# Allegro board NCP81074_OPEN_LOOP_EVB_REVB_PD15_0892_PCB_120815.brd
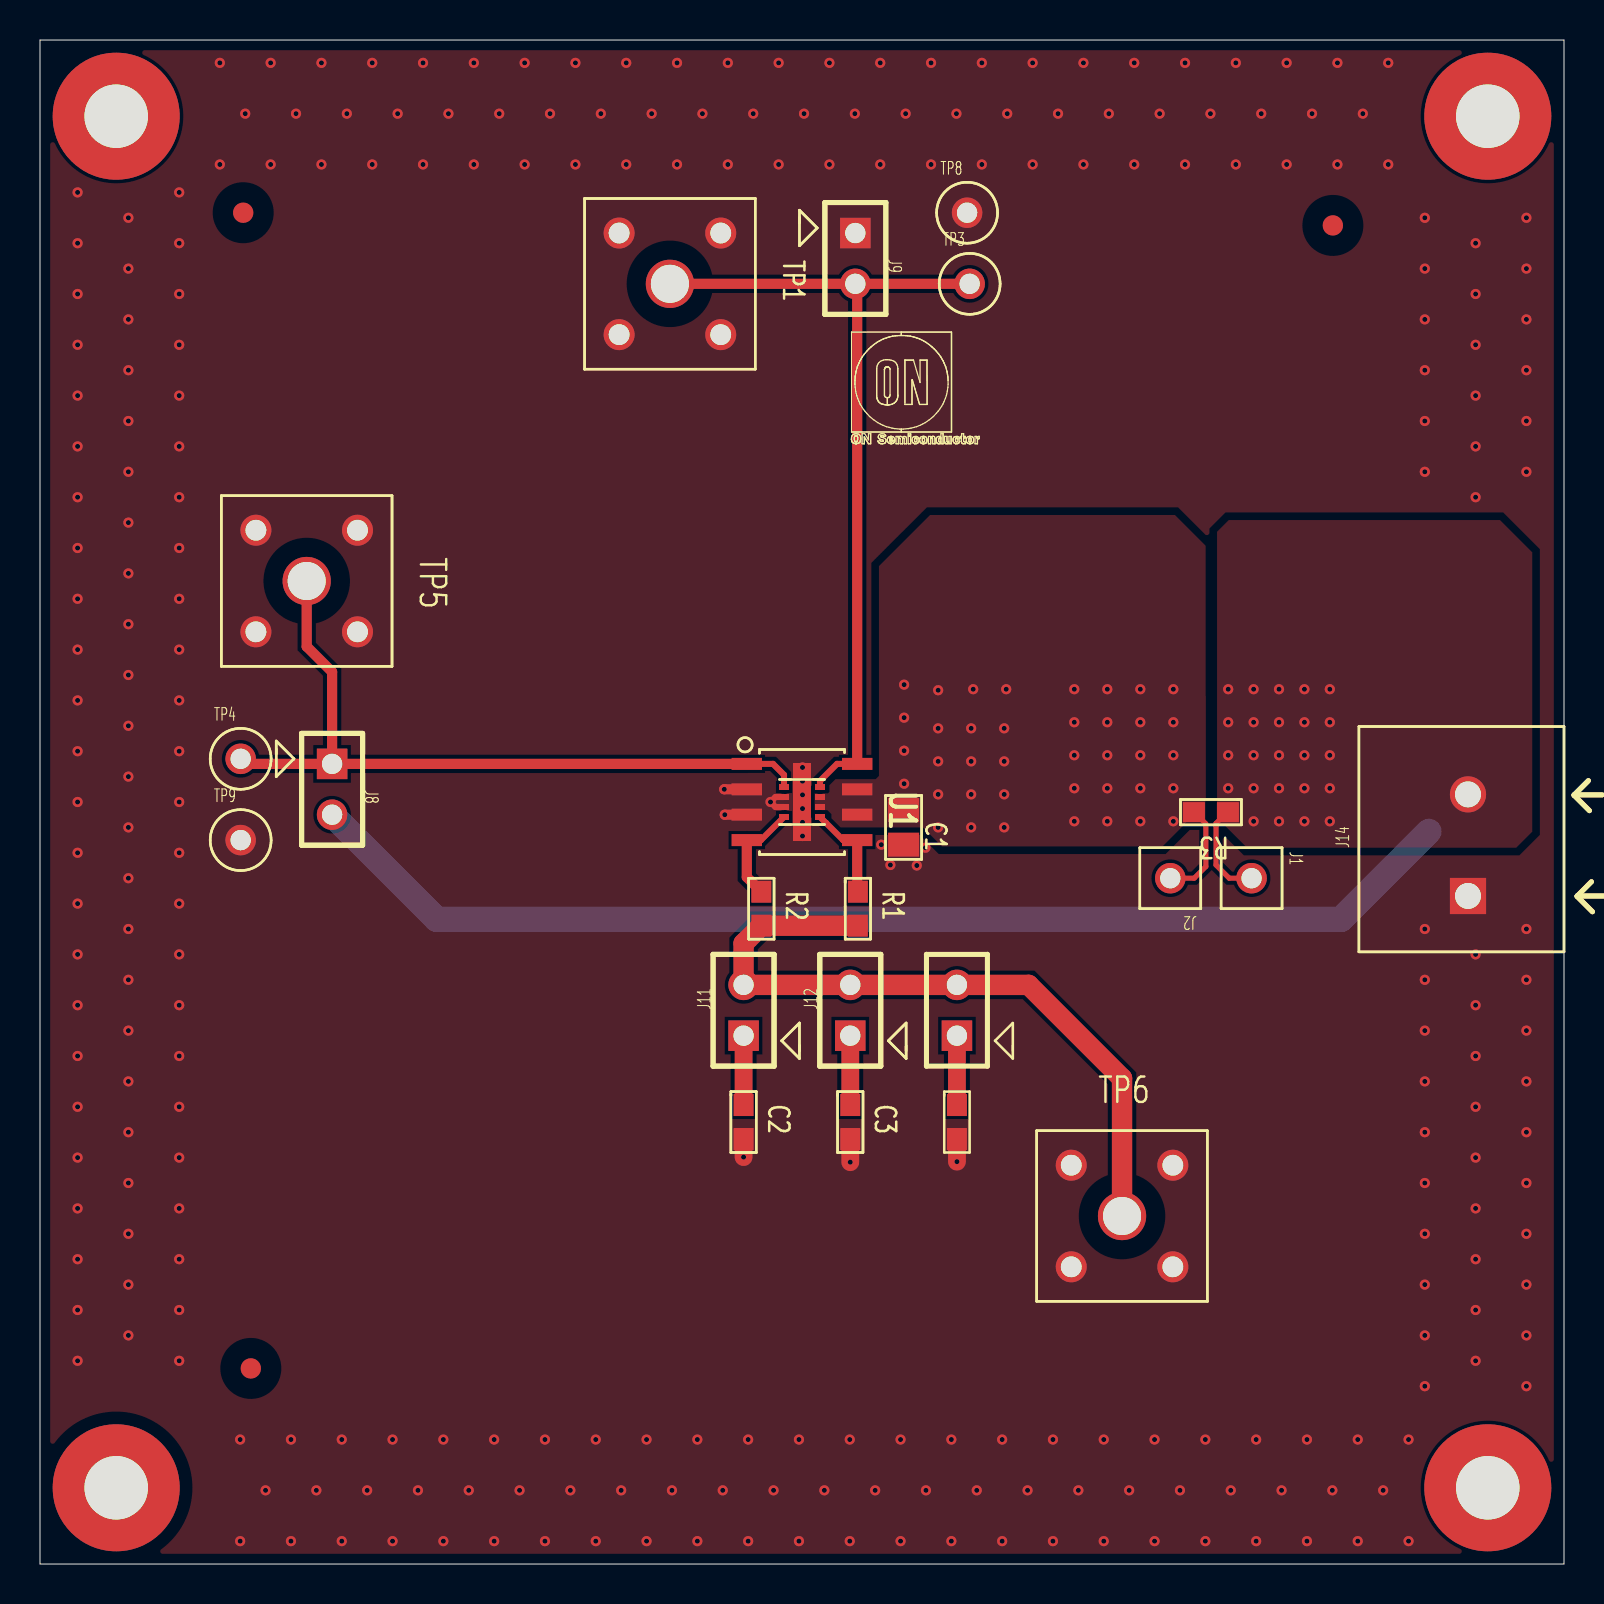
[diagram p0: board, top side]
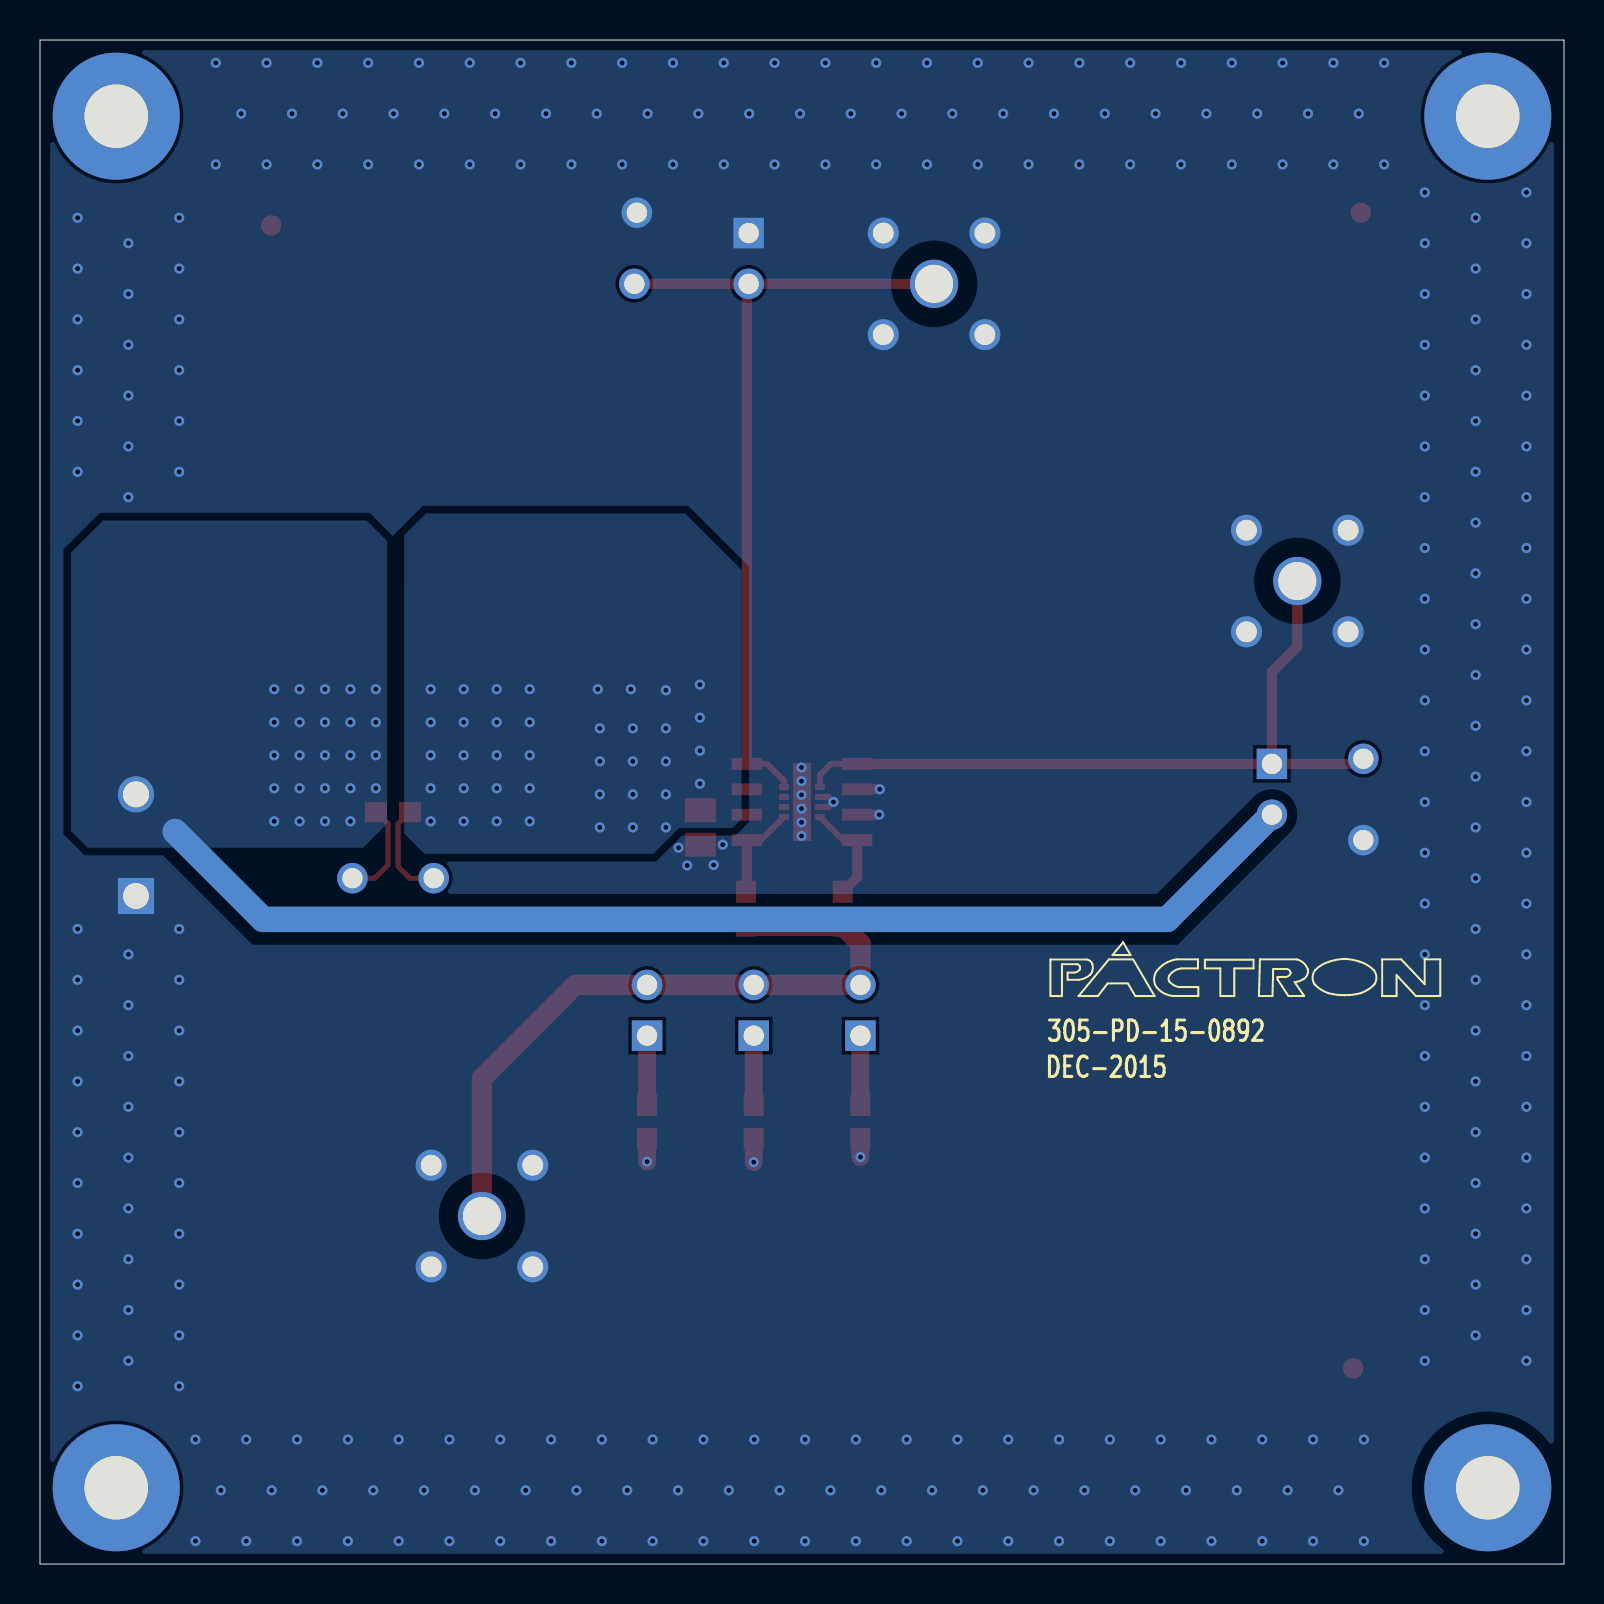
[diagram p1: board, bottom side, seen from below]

Outline 76.2 x 76.2 mm; copper layers: TOP, GND1#2, GND2#3, BOTTOM. Coordinates in mm from the lower left corner of the outline.
Outline path: 0,76.2 0,0 76.2,0 76.2,76.2 0,76.2

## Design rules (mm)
constraint set DEFAULT: min track width 0.254

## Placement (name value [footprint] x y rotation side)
C1  4.7uf  [0805]  43.18 36.83 270 top
C2  1nF  [0603]  35.18 22.1 270 top
C3  1.8nF  [0603]  40.51 22.1 270 top
C4  1.8nF  [0603]  45.85 22.1 270 top
J1  TP  [TRM1]  60.58 34.29 270 top
J2  TP  [TRM1]  56.52 34.29 180 top
J8  PEC36SAAN  [TERM3]  14.61 40.01 270 top
J9  PEC36SAAN  [TERM3]  40.77 66.55 270 top
J11  PEC36SAAN  [TERM3]  35.18 26.42 90 top
J12  PEC36SAAN  [TERM3]  40.51 26.42 90 top
J13  PEC36SAAN  [TERM3]  45.85 26.42 90 top
J14  2PIN/TERM BLK  [TRM2]  71.4 35.94 90 top
NOREF  -  []  76.2 76.2 0 top
NOREF#2  -  []  72.39 72.39 0 top
NOREF#3  -  [unnamed#2]  10.54 9.78 0 top
NOREF#4  -  [unnamed#2]  72.39 3.81 0 top
NOREF#5  -  [unnamed#2]  72.39 72.39 0 top
NOREF#6  -  [unnamed#2]  64.64 66.93 0 top
NOREF#7  -  [unnamed#2]  3.81 72.39 0 top
NOREF#8  -  []  72.39 72.39 0 top
NOREF#9  -  [unnamed#2]  3.81 3.81 0 top
NOREF#10  -  []  0 0 0 top
NOREF#11  -  [unnamed#2]  10.16 67.56 0 top
NOREF#12  -  []  0 0 0 top
NOREF#13  -  []  76.2 76.2 0 top
R1  1 OHM  [0603]  40.89 32.77 270 top
R2  1 OHM  [0603]  36.07 32.77 270 top
R3  0.1  [0603]  58.55 37.59 180 top
TP1  Probe Ground Tip  [SMA]  31.5 64.01 270 top
TP3  T POINT R  [TP40_60]  46.48 64.01 0 top
TP4  T POINT R  [TP40_60]  10.03 40.26 0 top
TP5  Probe Ground Tip  [SMA]  13.34 49.15 270 top
TP6  Probe Ground Tip  [SMA]  54.1 17.4 0 top
TP8  T POINT R  [TP40_60]  46.35 67.56 0 top
TP9  T POINT R  [TP40_60]  10.03 36.2 0 top
U1  NCP81074  [DFN8]  38.1 38.1 270 top

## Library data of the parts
C1 = CAP
C2-C4 = C
J1 J2 = TP_SQUARE
J8 J9 J11-J13 = JUMPER
J14 = Term_Blk_2_0.2
R1-R3 = R
TP1 TP5 TP6 = BNC_0
TP3 TP4 TP8 TP9 = T POINT R
U1 = ADP3418_4

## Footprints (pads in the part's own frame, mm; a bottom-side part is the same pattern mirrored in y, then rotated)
0603
  rect 1.1x1 smd: 1(-0.85,0) 2(0.85,0)
0805
  rect 1.2x1.55 smd: 1(-0.865,0) 2(0.865,0)
DFN8
  rect 0.6x1.52 smd: 1(-1.905,-2.76) 2(-0.635,-2.76) 3(0.635,-2.76) 4(1.905,-2.76) 5(1.905,2.76) 6(0.635,2.76) 7(-0.635,2.76) 8(-1.905,2.76)
  rect 0.3x0.5 smd: 1A(-0.75,-0.9) 2A(-0.25,-0.9) 3A(0.25,-0.9) 4A(0.75,-0.9) 5A(0.75,0.9) 6A(0.25,0.9) 7A(-0.25,0.9) 8A(-0.75,0.9)
  rect 3.9x0.9 smd: 9(0,0)
SMA
  round 2.413 hole 1.905: 1(0,0)
  round 1.549 hole 1.041: 2(2.54,-2.54) 3(2.54,2.54) 4(-2.54,2.54) 5(-2.54,-2.54)
TERM3
  rect 1.524x1.524 hole 1.016: 1(0,0)
  round 1.524 hole 1.016: 2(2.54,0)
TP40_60
  round 1.524 hole 1.016: 1(0,0)
TRM1
  round 1.524 hole 1.016: 1(0,0)
TRM2
  rect 1.808x1.808 hole 1.3: 1(-2.54,0)
  round 1.808 hole 1.3: 2(2.54,0)
unnamed#2
  round 1.016 smd: (0,0)

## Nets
12V: J1.1 J8.2 J14.2 R3.1
GND: C1.2 C2.2 C3.2 C4.2 J9.1 J14.1 TP1.2 TP1.3 TP1.4 TP1.5(SHIELD5) TP5.2 TP5.3 TP5.4 TP5.5(SHIELD5) TP6.2 TP6.3 TP6.4 TP6.5(SHIELD5) TP8.1(TP) TP9.1(TP) U1.2 U1.2A U1.3 U1.3A U1.9
N59573: C1.1 J2.1 R3.2 U1.6 U1.6A(VDDA) U1.7 U1.7A
N59818: J9.2 TP1.1 TP3.1(TP) U1.8 U1.8A
N60576: R2.1 U1.4 U1.4A
N60580: J11.2 J12.2 J13.2 R1.2 R2.2 TP6.1
N60608: R1.1 U1.5 U1.5A
N60828: C3.1 J12.1
N60830: C4.1 J13.1
N60852: C2.1 J11.1
N68500: J8.1 TP4.1(TP) TP5.1 U1.1 U1.1A

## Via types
v1: diameter 0.508, hole 0.254, TOP to BOTTOM, 339 vias

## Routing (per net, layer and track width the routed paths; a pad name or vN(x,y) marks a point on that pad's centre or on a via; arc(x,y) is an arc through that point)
12V: length 63.8
  TOP w0.254: J1.1 59.46,34.29 58.8,34.95 58.8,37.03 59.36,37.59 R3.1
  BOTTOM w1.27: 69.44,36.63 65.05,32.23 19.84,32.23 J8.2
  vias: v1(59.41,43.74) v1(59.41,42.09) v1(59.41,40.44) v1(59.41,38.79) v1(60.68,43.74) v1(60.68,42.09) v1(60.68,40.44) v1(60.68,38.79) v1(60.68,37.13) v1(61.95,43.74) v1(61.95,42.09) v1(61.95,40.44) v1(61.95,38.79) v1(61.95,37.13) v1(63.22,43.74) v1(63.22,42.09) v1(63.22,40.44) v1(63.22,38.79) v1(63.22,37.13) v1(64.49,43.74) v1(64.49,42.09) v1(64.49,40.44) v1(64.49,38.79) v1(64.49,37.13)
GND: length 7
  TOP w0.305: U1.2A 36.78,38.35 v1(36.53,38.1) 36.78,37.85 U1.3A
  TOP w0.508: U1.3 v1(34.24,37.47) ; U1.2 v1(34.21,38.73)
  TOP w0.889: C2.2 v1(35.18,20.35) ; C3.2 v1(40.51,20.09) ; C4.2 v1(45.85,20.12)
  vias: v1(1.88,68.58) v1(1.88,66.04) v1(1.88,63.5) v1(1.88,60.96) v1(1.88,58.42) v1(1.88,55.88) v1(1.88,53.34) v1(1.88,50.8) v1(1.88,48.26) v1(1.88,45.72) v1(1.88,43.18) v1(1.88,40.64) v1(1.88,38.1) v1(1.88,35.56) v1(1.88,33.02) v1(1.88,30.48) v1(1.88,27.94) v1(1.88,25.4) v1(1.88,22.86) v1(1.88,20.32) v1(1.88,17.78) v1(1.88,15.24) v1(1.88,12.7) v1(1.88,10.16) v1(4.42,67.31) v1(4.42,64.77) v1(4.42,62.23) v1(4.42,59.69) v1(4.42,57.15) v1(4.42,54.61) v1(4.42,52.07) v1(4.42,49.53) v1(4.42,46.99) v1(4.42,44.45) v1(4.42,41.91) v1(4.42,39.37) v1(4.42,36.83) v1(4.42,34.29) v1(4.42,31.75) v1(4.42,29.21) v1(4.42,26.67) v1(4.42,24.13) v1(4.42,21.59) v1(4.42,19.05) v1(4.42,16.51) v1(4.42,13.97) v1(4.42,11.43) v1(6.96,68.58) v1(6.96,66.04) v1(6.96,63.5) v1(6.96,60.96) v1(6.96,58.42) v1(6.96,55.88) v1(6.96,53.34) v1(6.96,50.8) v1(6.96,48.26) v1(6.96,45.72) v1(6.96,43.18) v1(6.96,40.64) v1(6.96,38.1) v1(6.96,35.56) v1(6.96,33.02) v1(6.96,30.48) v1(6.96,27.94) v1(6.96,25.4) v1(6.96,22.86) v1(6.96,20.32) v1(6.96,17.78) v1(6.96,15.24) v1(6.96,12.7) v1(6.96,10.16) v1(8.99,75.06) v1(8.99,69.98) v1(10.01,6.22) v1(10.01,1.14) v1(10.26,72.52) v1(11.28,3.68) v1(11.53,75.06) v1(11.53,69.98) v1(12.55,6.22) v1(12.55,1.14) v1(12.8,72.52) v1(13.82,3.68) v1(14.07,75.06) v1(14.07,69.98) v1(15.09,6.22) v1(15.09,1.14) v1(15.34,72.52) v1(16.36,3.68) v1(16.61,75.06) v1(16.61,69.98) v1(17.63,6.22) v1(17.63,1.14) v1(17.88,72.52) v1(18.9,3.68) v1(19.15,75.06) v1(19.15,69.98) v1(20.17,6.22) v1(20.17,1.14) v1(20.42,72.52) v1(21.44,3.68) v1(21.69,75.06) v1(21.69,69.98) v1(22.71,6.22) v1(22.71,1.14) v1(22.96,72.52) v1(23.98,3.68) v1(24.23,75.06) v1(24.23,69.98) v1(25.25,6.22) v1(25.25,1.14) v1(25.5,72.52) v1(26.52,3.68) v1(26.77,75.06) v1(26.77,69.98) v1(27.79,6.22) v1(27.79,1.14) v1(28.04,72.52) v1(29.06,3.68) v1(29.31,75.06) v1(29.31,69.98) v1(30.33,6.22) v1(30.33,1.14) v1(30.58,72.52) v1(31.6,3.68) v1(31.85,75.06) v1(31.85,69.98) v1(32.87,6.22) v1(32.87,1.14) v1(33.12,72.52) v1(34.14,3.68) v1(34.39,75.06) v1(34.39,69.98) v1(35.41,6.22) v1(35.41,1.14) v1(35.66,72.52) v1(36.68,3.68) v1(36.93,75.06) v1(36.93,69.98) v1(37.95,6.22) v1(37.95,1.14) v1(38.13,39.83) v1(38.13,39.14) v1(38.13,38.46) v1(38.13,37.77) v1(38.13,37.08) v1(38.13,36.4) v1(38.2,72.52) v1(39.22,3.68) v1(39.47,75.06) v1(39.47,69.98) v1(40.49,6.22) v1(40.49,1.14) v1(40.74,72.52) v1(41.76,3.68) v1(42.01,75.06) v1(42.01,69.98) v1(42.06,35.97) v1(42.52,34.95) v1(43.03,6.22) v1(43.03,1.14) v1(43.28,72.52) v1(43.84,34.92) v1(44.27,35.81) v1(44.3,3.68) v1(44.55,75.06) v1(44.55,69.98) v1(45.57,6.22) v1(45.57,1.14) v1(45.82,72.52) v1(46.84,3.68) v1(47.09,75.06) v1(47.09,69.98) v1(48.11,6.22) v1(48.11,1.14) v1(48.36,72.52) v1(49.38,3.68) v1(49.63,75.06) v1(49.63,69.98) v1(50.65,6.22) v1(50.65,1.14) v1(50.9,72.52) v1(51.92,3.68) v1(52.17,75.06) v1(52.17,69.98) v1(53.19,6.22) v1(53.19,1.14) v1(53.44,72.52) v1(54.46,3.68) v1(54.71,75.06) v1(54.71,69.98) v1(55.73,6.22) v1(55.73,1.14) v1(55.98,72.52) v1(57,3.68) v1(57.25,75.06) v1(57.25,69.98) v1(58.27,6.22) v1(58.27,1.14) v1(58.52,72.52) v1(59.54,3.68) v1(59.79,75.06) v1(59.79,69.98) v1(60.81,6.22) v1(60.81,1.14) v1(61.06,72.52) v1(62.08,3.68) v1(62.33,75.06) v1(62.33,69.98) v1(63.35,6.22) v1(63.35,1.14) v1(63.6,72.52) v1(64.62,3.68) v1(64.87,75.06) v1(64.87,69.98) v1(65.89,6.22) v1(65.89,1.14) v1(66.14,72.52) v1(67.16,3.68) v1(67.41,75.06) v1(67.41,69.98) v1(68.43,6.22) v1(68.43,1.14) v1(69.24,67.31) v1(69.24,64.77) v1(69.24,62.23) v1(69.24,59.69) v1(69.24,57.15) v1(69.24,54.61) v1(69.24,31.75) v1(69.24,29.21) v1(69.24,26.67) v1(69.24,24.13) v1(69.24,21.59) v1(69.24,19.05) v1(69.24,16.51) v1(69.24,13.97) v1(69.24,11.43) v1(69.24,8.89) v1(71.78,66.04) v1(71.78,63.5) v1(71.78,60.96) v1(71.78,58.42) v1(71.78,55.88) v1(71.78,53.34) v1(71.78,30.48) v1(71.78,27.94) v1(71.78,25.4) v1(71.78,22.86) v1(71.78,20.32) v1(71.78,17.78) v1(71.78,15.24) v1(71.78,12.7) v1(71.78,10.16) v1(74.32,67.31) v1(74.32,64.77) v1(74.32,62.23) v1(74.32,59.69) v1(74.32,57.15) v1(74.32,54.61) v1(74.32,31.75) v1(74.32,29.21) v1(74.32,26.67) v1(74.32,24.13) v1(74.32,21.59) v1(74.32,19.05) v1(74.32,16.51) v1(74.32,13.97) v1(74.32,11.43) v1(74.32,8.89)
N59573: length 5
  TOP w0.254: R3.2 57.71,37.59 58.29,37.01 58.29,34.87 57.71,34.29 J2.1
  vias: v1(43.21,43.97) v1(43.21,42.32) v1(43.21,40.67) v1(43.21,39.01) v1(44.91,43.69) v1(44.91,41.78) v1(44.91,40.13) v1(44.91,38.48) v1(44.91,36.83) v1(46.56,41.78) v1(46.56,40.13) v1(46.56,38.48) v1(46.56,36.83) v1(46.66,43.74) v1(48.21,41.78) v1(48.21,40.13) v1(48.21,38.48) v1(48.21,36.83) v1(48.31,43.74) v1(51.71,43.74) v1(51.71,42.09) v1(51.71,40.44) v1(51.71,38.79) v1(51.71,37.13) v1(53.37,43.74) v1(53.37,42.09) v1(53.37,40.44) v1(53.37,38.79) v1(53.37,37.13) v1(55.02,43.74) v1(55.02,42.09) v1(55.02,40.44) v1(55.02,38.79) v1(55.02,37.13) v1(56.67,43.74) v1(56.67,42.09) v1(56.67,40.44) v1(56.67,38.79) v1(56.67,37.13)
N59818: length 41.5
  TOP w0.305: U1.8 39.85,40.01 39,39.15 U1.8A
  TOP w0.508: U1.8 40.86,63.92 J9.2 ; TP3.1 J9.2 ; J9.2 TP1.1
N60576: length 5.2
  TOP w0.305: U1.4 36.05,36.2 U1.4A
  TOP w0.508: R2.1 35.34,34.34 U1.4
N60580: length 35.9
  TOP w1.016: R1.2 R2.2 35.18,31.03 J11.2 J12.2 J13.2 49.43,28.96 54.1,24.28 TP6.1
N60608: length 4.9
  TOP w0.305: U1.5 40.16,36.2 39.29,37.06 39.29,37.06 U1.5A
  TOP w0.508: U1.5 40.86,33.65 R1.1
N60828: length 3.5
  TOP w0.889: J12.1 C3.1
N60830: length 3.5
  TOP w0.889: J13.1 C4.1
N60852: length 3.5
  TOP w0.889: C2.1 J11.1
N68500: length 38.4
  TOP w0.305: U1.1A 37.2,39.46 36.65,40.01 U1.1
  TOP w0.508: U1.1 J8.1 ; J8.1 14.61,44.6 13.34,45.87 TP5.1 13.34,49.78 ; J8.1 10.29,40.01 TP4.1

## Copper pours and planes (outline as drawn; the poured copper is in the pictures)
12V on TOP: 74.61,36.61 73.81,35.81 60.35,35.81 59.16,37.01 58.85,37.01 58.85,51.61 59.44,52.2 73,52.2 74.61,50.58
12V on BOTTOM: 58.85,37.01 58.85,51.16 59.87,52.17 73.05,52.17 74.65,50.57 74.65,36.65 73.81,35.81 60.05,35.81
GND on TOP, GND1#2, GND2#3: 0.51,0.51 0.51,75.69 75.69,75.69 75.69,0.51 ; 4 cut-outs
GND on BOTTOM: 0.51,0.51 0.51,75.69 75.69,75.69 75.69,0.51 ; 5 cut-outs
N59573 on TOP: 44.15,36.83 45.1,35.88 56.12,35.88 57.33,37.08 58.27,37.08 58.27,38.23 58.29,38.25 58.29,43.41 58.28,43.42 58.28,50.91 56.74,52.45 44.5,52.45 41.95,49.9 41.95,39.41 41.78,39.24 39.78,39.24 39.47,38.94 39.47,38.61 39.4,38.53 38.73,38.53 38.73,37.69 39.37,37.69 39.57,37.49 39.57,37.01 39.75,36.83
N59573 on BOTTOM: 57.99,49.35 57.99,36.53 56.97,35.51 45.54,35.51 44.25,36.8 41.58,36.8 41.12,37.26 41.12,49.71 43.94,52.53 56.9,52.53 57.99,51.44 57.99,51.43 57.99,49.35

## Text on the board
BOTTOM: BOTTOM
Ref Des/Assembly Bottom: SECONDARY SIDE ASSEMBLY VIEWED FROM SECONDARY SIDE
Board Geometry/Soldermask Bottom: SOLDERMASK_BOTTOM
Ref Des/Silkscreen Bottom: 305-PD-15-0892 | DEC-2015
User.Comments: DEC 2015 | NCP81074_OPEN_LOOP_EVB_REVB
Ref Des/Assembly Top: NCP81074_OPEN_LOOP_EVB_REVB
Board Geometry/Soldermask Top: SOLDERMASK_TOP
GND1#2: GND1#2
GND2#3: GND2#3
User.16: TOP
User.20: ASSEMBLY TOP
User.24: PASTEMASK_BOTTOM
User.25: PASTEMASK_TOP
User.32: SILK_TOP
User.37: BOARD DIMENSIONS ARE IN MILS(MM) | FAB | TOP | GND1#2 | GND2#3 | BOTTOM | STACKUP: | 2 OZ COPPER | 1) FABRICATE BOARD PER IPC-A-600G | 2) MATERIAL FR4 4 LAYER BOARD. | 3) BOARD THICKNESS : 0.5 MM(+/- 10 %) | 4) MINIMUM PLATING IN ALL THE THROUGH HOLE SHALL BE 0.001 INCH Cu. | 5) ALL HOLES ARE PLATED THROUGH UNLESS OTHERWISE SPECIFIED. | 6) HOLE SIZE ARE FINISHED SIZE. | 7) SOLDER MASK BOTH SIDE WITH GREEN LIQUID PHOTO IMAGABLE. | 8) FOR LAYER BUILD UP SEE STACK UP DETAIL. | 9) SILKSCREEN BOTH SIDE "WHITE EPOXY" OVER SOLDER MASK | NOTES : | 17) CLIP SILKSCREEEN ON NO MASK AREA. | 15) BOARD MUST BE ROHS COMPLAINT. | 10) DEBURR ALL SHARP EDGES | 11) BOW AND TWIST: SHOULD NOT EXCEED 0.007" PER INCH. | 12) PLATED PADS ON TOP AND BOTTOM MUST BE SAME HEIGHT AS CONDUCTOR PAD AND TRACE | 13) PLATING: LEAD FREE GOLD FINISH. | 16) REMOVE ALL UNUSED PADS IN ALL INNER LAYERS | 14) NO VENDOR LOGO OR NAME ON THE BOARD. | 18) MASK OPENING SHOULD BE AS LIKE GERBER FILE,DON'T DO ANY GANG MASK OPENING | 19) ARTWORKS SHOULD NOT BE CHANGED WITHOUT PRIOR APPROVAL FROM PACTRON
User.38: BOARD OUTLINE
User.39: INSTALL AS WIRE | FACING OUT SIDE.
User.45: FIGURE | SIZE | 10.0 | 40.0 | 41.0 | 51.18 | 75.0 | 125.0 | DRILL CHART: TOP to BOTTOM | ALL UNITS ARE IN MILS | TOLERANCE | +3.0/-10.0 | +3.0/-3.0 | +3.0/-0.0 | +2.0/-2.0 | PLATED | NON-PLATED | QTY | 339 | 16 | 12 | 2 | 3 | 4
